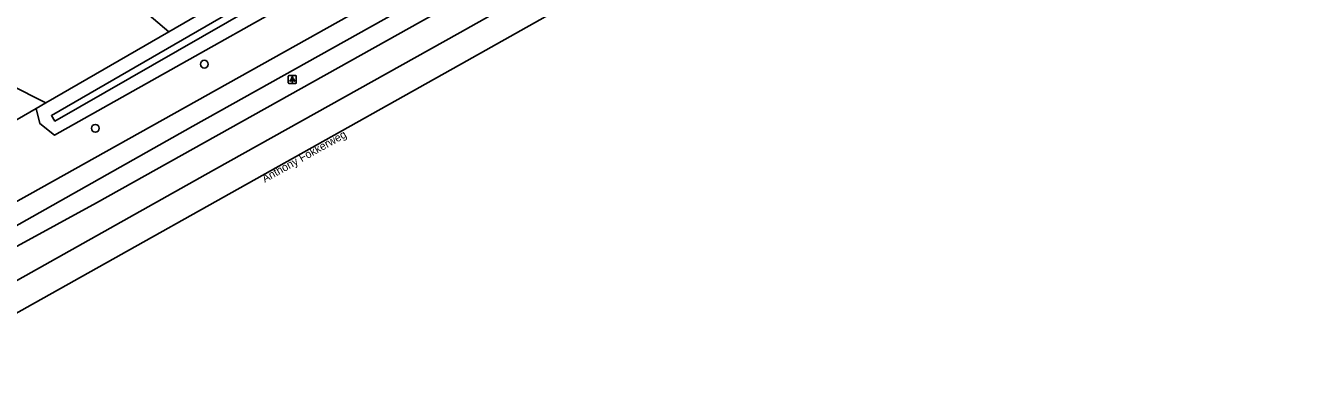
# Model space of a CAD drawing. Extents: x 156141 to 158132, y 385651 to 388399.
# Drawn here: x 157171.8 to 157330, y 386114.3 to 386160 of the extents above; entities that cross this region are included whole.
import ezdxf

# ---------------------------------------------------------------- set-up
doc = ezdxf.new("R2010")
doc.units = 0
for name, color, linetype in [('IMGEO_Boom', 7, 'Continuous'), ('IMGEO_Fietspad_gesloten', 7, 'Continuous'), ('IMGEO_Groenvoorziening', 7, 'Continuous'), ('IMGEO_Lichtpunt', 7, 'Continuous'), ('IMGEO_Openbare_ruimte_label', 7, 'Continuous'), ('IMGEO_Rijbaan_regionaal_gesloten', 7, 'Continuous'), ('IMGEO_Waterloop', 7, 'Continuous')]:
    doc.layers.add(name, color=color, linetype=linetype)

msp = doc.modelspace()

# ---------------------------------------------------------------- linework, layer by layer
at = {"layer": 'IMGEO_Boom'}
for centre in [(157194.13, 386155.17), (157180.52, 386147.15)]:
    msp.add_circle(centre, 0.489, dxfattribs=at)
at = {"layer": 'IMGEO_Fietspad_gesloten'}
for points in [[(157144.44, 386123.38), (157172.33, 386138.9), (157315.85, 386219.29)], [(157286.94, 386200.22), (157277.15, 386194.68), (157192.69, 386147.4), (157144.36, 386120.11)]]:
    msp.add_lwpolyline(points, dxfattribs=at)
at = {"layer": 'IMGEO_Groenvoorziening'}
for points in [[(157218.02, 386175.67), (157218.42, 386175.65), (157218.95, 386175.47), (157219.48, 386174.7), (157219.55, 386174.55), (157219.98, 386173.67), (157220.08, 386173.46), (157220.38, 386172.57), (157220.35, 386171.61), (157175.4, 386146.31), (157173.59, 386147.74), (157173.12, 386149.64)], [(157189.71, 386159.21), (157218.02, 386175.67)], [(157185.05, 386163.19), (157189.71, 386159.21)], [(157189.71, 386159.21), (157174.32, 386150.33)], [(157174.32, 386150.33), (157165.3, 386154.9)], [(157173.12, 386149.64), (157168.35, 386146.89), (157167.3, 386146.24)], [(157174.32, 386150.33), (157173.12, 386149.64)]]:
    msp.add_lwpolyline(points, dxfattribs=at)
at = {"layer": 'IMGEO_Lichtpunt'}
for p, q in [((157205.54, 386153.76), (157204.73, 386153.76)), ((157205.54, 386153.76), (157204.73, 386153.76)), ((157204.63, 386153.67), (157204.63, 386152.86)), ((157204.63, 386153.67), (157204.63, 386152.86)), ((157204.73, 386152.76), (157205.54, 386152.76)), ((157204.73, 386152.76), (157205.54, 386152.76)), ((157205.63, 386152.86), (157205.63, 386153.67)), ((157205.63, 386152.86), (157205.63, 386153.67))]:
    msp.add_line(p, q, dxfattribs=at)
for points in [[(157205.01, 386153.33), (157205.05, 386153.3), (157204.86, 386153.04), (157204.82, 386153.07), (157205.01, 386153.33)], [(157205.11, 386153.28), (157205.16, 386153.28), (157205.16, 386152.96), (157205.11, 386152.96), (157205.11, 386153.28)], [(157205.22, 386153.3), (157205.26, 386153.33), (157205.44, 386153.07), (157205.41, 386153.04), (157205.22, 386153.3)]]:
    msp.add_lwpolyline(points, dxfattribs=at)
msp.add_circle((157205.13, 386153.46), 0.0994, dxfattribs=at)
for centre, start, end in [((157204.73, 386153.67), 90, 180), ((157204.73, 386153.67), 90, 180), ((157205.54, 386153.67), 0, 90), ((157205.54, 386153.67), 0, 90), ((157204.73, 386152.86), 180, 270), ((157204.73, 386152.86), 180, 270), ((157205.54, 386152.86), 270, 0), ((157205.54, 386152.86), 270, 360)]:
    msp.add_arc(centre, 0.0946, start, end, dxfattribs=at)
at = {"layer": 'IMGEO_Rijbaan_regionaal_gesloten'}
for points in [[(157330.01, 386211.25), (157329.16, 386212.75), (157262.74, 386175.77), (157226.92, 386155.61), (157153.3, 386114.3)], [(157264.12, 386180.57), (157226.11, 386159.14), (157195.28, 386141.9), (157149.68, 386116.28)], [(157230.38, 386165.68), (157180.67, 386137.84), (157145.46, 386118.58)]]:
    msp.add_lwpolyline(points, dxfattribs=at)
at = {"layer": 'IMGEO_Waterloop'}
msp.add_lwpolyline([(157218.61, 386172.88), (157218.23, 386173.79), (157175.03, 386148.74), (157175.47, 386148.06), (157218.61, 386172.88)], dxfattribs=at)

# ---------------------------------------------------------------- texts
at = {"layer": 'IMGEO_Openbare_ruimte_label'}
msp.add_text('Anthony Fokkerweg', height=1, rotation=29.2048, dxfattribs=at).set_placement((157201.69, 386140.33))

doc.saveas('drawing.dxf')
